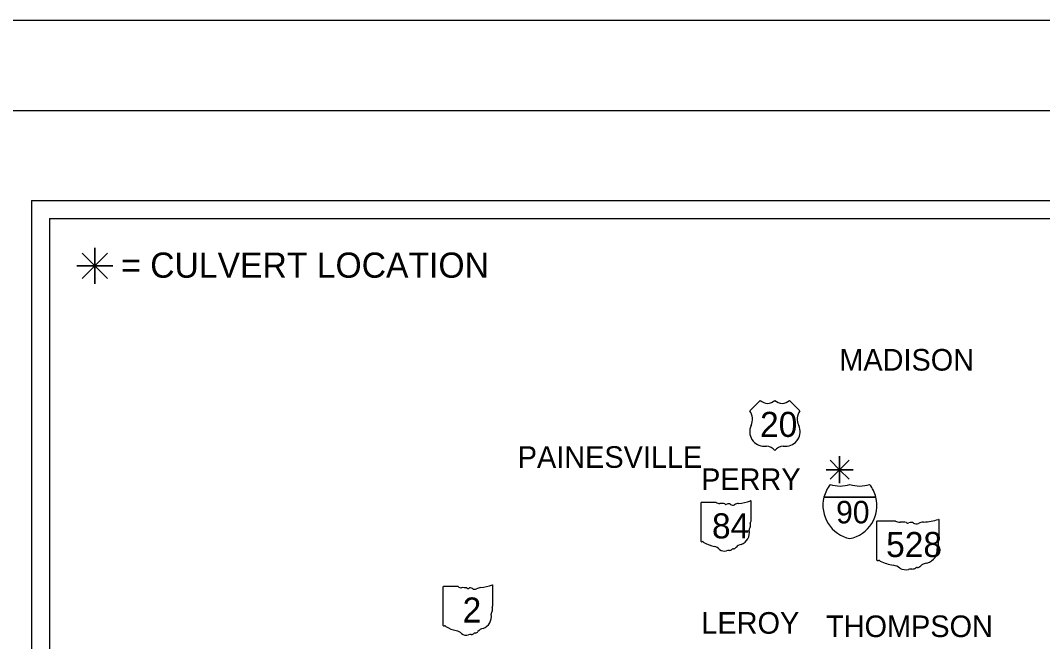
# Model space of a CAD drawing. Extents: x -1 to 48.3, y -9.3 to 22.
# Drawn here: x 1.94 to 7.62, y 18.55 to 22 of the extents above; entities that cross this region are included whole.
import ezdxf

# ---------------------------------------------------------------- set-up
doc = ezdxf.new("R2010")
doc.units = 0
for name, color, linetype in [('GM_X_Adjacent_County_Text', 7, 'Continuous'), ('GM_X_County', 7, 'Continuous'), ('GM_X_County_Road', 7, 'Continuous'), ('GM_X_Minor_Lake', 7, 'Continuous'), ('GM_X_Minor_Lake_Text', 7, 'Continuous'), ('GM_X_Minor_River_Text', 7, 'Continuous'), ('GM_X_Township', 7, 'Continuous')]:
    doc.layers.add(name, color=color, linetype=linetype)

msp = doc.modelspace()

# ---------------------------------------------------------------- linework, layer by layer
at = {"layer": 'GM_X_Adjacent_County_Text'}
msp.add_lwpolyline([(0, 0), (34, 0), (34, 22), (0, 22)], close=True, dxfattribs=at)
at = {"layer": 'GM_X_County'}
for p, q in [((2, 21), (2, 14)), ((2, 21), (9, 21)), ((2.1, 20.9), (2.1, 14.1)), ((2.1, 20.9), (8.9, 20.9))]:
    msp.add_line(p, q, dxfattribs=at)
at = {"layer": 'GM_X_County_Road'}
for p, q in [((5.7217, 19.3193), (5.7217, 19.108)), ((5.806, 19.3229), (5.7245, 19.3229)), ((6.0002, 19.2176), (6.0002, 19.3282)), ((6.0001, 19.2176), (6.0002, 19.2176)), ((6.6978, 19.2155), (6.6978, 19.0042)), ((6.8032, 19.2191), (6.7013, 19.2191)), ((7.0459, 19.1138), (7.0459, 19.2244)), ((7.0458, 19.1138), (7.0459, 19.1138)), ((4.2872, 18.8519), (4.2872, 18.6405)), ((4.3715, 18.8555), (4.29, 18.8555)), ((4.5657, 18.7502), (4.5657, 18.8607)), ((4.5656, 18.7502), (4.5657, 18.7502))]:
    msp.add_line(p, q, dxfattribs=at)
for centre, radius, start, end in [((5.7249, 19.3197), 0.00323, 98.1301, 188.1301), ((5.8254, 19.3475), 0.0313, 231.6195, 271.1119), ((5.9386, 19.2584), 0.0594, 97.3462, 120.7689), ((5.901, 19.611), 0.2953, 275.8445, 288.9065), ((5.9971, 19.3286), 0.0031, 351.8621, 97.738), ((5.8358, 19.2043), 0.1123, 80.4867, 94.9883), ((5.8613, 19.3208), 0.00903, 219.7921, 297.1024), ((5.8746, 19.2964), 0.0188, 54.4667, 119.1411), ((5.8988, 19.3299), 0.0226, 233.8562, 294.8282), ((5.9995, 19.2095), 0.0048, 107.944, 210.337), ((5.9689, 19.1955), 0.0288, 340.033, 23.6496), ((5.9969, 19.2172), 0.00332, 289.6038, 7.7341), ((5.9175, 19.1573), 0.0739, 292.3089, 8.9858), ((6.0113, 19.1713), 0.021, 136.8065, 186.9296), ((5.725, 19.1075), 0.00325, 171.9584, 258.3066), ((5.7254, 19.1291), 0.0248, 267.339, 280.6039), ((5.7305, 19.0958), 0.00895, 29.7484, 93.2717), ((5.8436, 19.2856), 0.2132, 240.4129, 257.1985), ((5.78, 19.013), 0.0667, 47.1842, 75.836), ((5.8522, 19.0947), 0.0423, 230.7004, 286.2918), ((5.8766, 19.0217), 0.0348, 85.6951, 111.2099), ((5.8797, 19.0789), 0.0226, 268.777, 315.5493), ((5.9001, 19.0584), 0.00635, 65.7517, 132.6484), ((5.8974, 19.0875), 0.0239, 282.8732, 323.2771), ((5.9487, 19.0486), 0.0404, 94.4031, 142.5768), ((4.4665, 19.1436), 0.2953, 275.8445, 288.9065), ((4.5626, 18.8612), 0.0031, 351.8621, 97.738), ((4.2904, 18.8523), 0.00323, 98.1301, 188.1301), ((4.3909, 18.88), 0.0313, 231.6195, 271.1119), ((4.4013, 18.7369), 0.1123, 80.4867, 94.9883), ((4.4268, 18.8534), 0.00903, 219.7921, 297.1024), ((4.4401, 18.829), 0.0188, 54.4667, 119.1411), ((4.4643, 18.8625), 0.0226, 233.8562, 294.8282), ((4.5041, 18.791), 0.0594, 97.3462, 120.7689), ((4.5624, 18.7498), 0.00332, 289.6038, 7.7341), ((4.483, 18.6899), 0.0739, 292.3089, 8.9858), ((4.5768, 18.7039), 0.021, 136.8065, 186.9296), ((4.565, 18.7421), 0.0048, 107.944, 210.337), ((4.5344, 18.7281), 0.0288, 340.033, 23.6496), ((4.2905, 18.6401), 0.00325, 171.9584, 258.3066), ((4.2909, 18.6617), 0.0248, 267.339, 280.6039), ((4.296, 18.6284), 0.00895, 29.7484, 93.2717), ((4.4091, 18.8182), 0.2132, 240.4129, 257.1985), ((4.3455, 18.5456), 0.0667, 47.1842, 75.836), ((4.4177, 18.6273), 0.0423, 230.7004, 286.2918), ((4.4421, 18.5542), 0.0348, 85.6951, 111.2099), ((4.4452, 18.6115), 0.0226, 268.777, 315.5493), ((4.4656, 18.591), 0.00635, 65.7517, 132.6484), ((4.4629, 18.6201), 0.0239, 282.8732, 323.2771), ((4.5142, 18.5812), 0.0404, 94.4031, 142.5768)]:
    msp.add_arc(centre, radius, start, end, dxfattribs=at)
for centre, major_axis, start_param, end_param in [((6.7018, 19.2159), (0.00403, 0), 1.712693, 3.28349), ((6.8275, 19.2437), (0.0391, 0), 4.042523, 4.731795), ((6.8404, 19.1005), (0.1404, 0), 1.404758, 1.657858), ((6.8723, 19.217), (0.0113, 0), 3.836095, 5.185415), ((6.8889, 19.1926), (0.0235, 0), 0.950623, 2.079405), ((6.9191, 19.2261), (0.0282, 0), 4.081561, 5.145723), ((6.969, 19.1546), (0.0743, 0), 1.699011, 2.107814), ((6.9219, 19.5072), (0.3691, 0), 4.814394, 5.042369), ((7.042, 19.2248), (0.00387, 0), 6.141152, 7.989035), ((7.045, 19.1057), (0.006, 0), 1.883978, 3.671073), ((7.0068, 19.0917), (0.036, 0), 5.934695, 6.695948), ((7.0417, 19.1134), (0.00415, 0), 5.05454, 6.418171), ((6.9426, 19.0535), (0.0923, 0), 5.101752, 6.440018), ((7.0598, 19.0675), (0.0262, 0), 2.387724, 3.262537), ((6.7019, 19.0037), (0.00407, 0), 3.00124, 4.508301), ((6.7025, 19.0253), (0.031, 0), 4.665946, 4.897461), ((6.7088, 18.992), (0.0112, 0), 0.519207, 1.627899), ((6.8501, 19.1818), (0.2665, 0), 4.195997, 4.488961), ((6.9815, 18.9448), (0.0506, 0), 1.647645, 2.488434), ((6.7707, 18.9092), (0.0834, 0), 0.823519, 1.323587), ((6.8609, 18.9909), (0.0529, 0), 4.026481, 4.996735), ((6.8915, 18.9179), (0.0435, 0), 1.495662, 1.94098), ((6.8953, 18.9751), (0.0282, 0), 4.691044, 5.507374), ((6.9208, 18.9546), (0.00794, 0), 1.147584, 2.315152), ((6.9174, 18.9837), (0.0298, 0), 4.937069, 5.64225)]:
    msp.add_ellipse(centre, major_axis=major_axis, ratio=0.8, start_param=start_param, end_param=end_param, dxfattribs=at)
at = {"layer": 'GM_X_Minor_Lake'}
msp.add_lwpolyline([(1.5, 21.5), (33.5, 21.5), (33.5, 0.5), (1.5, 0.5)], close=True, dxfattribs=at)
at = {"layer": 'GM_X_Minor_Lake_Text'}
for p, q in [((6.4055, 19.3517), (6.694, 19.3517)), ((6.694, 19.3517), (6.4055, 19.3517)), ((6.694, 19.3517), (6.4055, 19.3517))]:
    msp.add_line(p, q, dxfattribs=at)
for centre, start, end in [((6.5872, 19.3057), 141.669, 165.8066), ((6.4949, 19.6013), 253.0091, 286.9909), ((6.6045, 19.6013), 253.0091, 286.9909), ((6.5122, 19.3057), 14.1934, 38.331), ((6.5872, 19.3057), 165.8066, 258.463), ((6.5122, 19.3057), 281.537, 14.1934)]:
    msp.add_arc(centre, 0.1875, start, end, dxfattribs=at)
at = {"layer": 'GM_X_Minor_River_Text'}
for p, q in [((6.0513, 19.8897), (5.9933, 19.8317)), ((6.2718, 19.8317), (6.2138, 19.8897)), ((6.0745, 19.6344), (6.0861, 19.6344)), ((6.1789, 19.6344), (6.1906, 19.6344))]:
    msp.add_line(p, q, dxfattribs=at)
for centre, radius, start, end in [((6.0919, 19.9311), 0.058, 225.573, 314.427), ((6.1731, 19.9311), 0.058, 225.573, 314.427), ((5.9268, 19.7851), 0.0812, 334.5471, 35.0009), ((6.3383, 19.7851), 0.0812, 144.9991, 205.4529), ((6.0736, 19.7156), 0.0812, 154.8319, 270.6383), ((6.1915, 19.7156), 0.0812, 269.3617, 25.1681), ((6.0861, 19.5764), 0.058, 36.8699, 90), ((6.1789, 19.5764), 0.058, 90, 143.1301)]:
    msp.add_arc(centre, radius, start, end, dxfattribs=at)
at = {"layer": 'GM_X_Township'}
for points in [[(2.2526, 20.6366), (2.3526, 20.6366), (2.2819, 20.7073), (2.3526, 20.6366), (2.3526, 20.7366), (2.3526, 20.6366), (2.4233, 20.7073), (2.3526, 20.6366), (2.4526, 20.6366), (2.3526, 20.6366), (2.4233, 20.5659), (2.3526, 20.6366), (2.3526, 20.5366), (2.3526, 20.6366), (2.2819, 20.5659), (2.3526, 20.6366)], [(6.4172, 19.5043), (6.4922, 19.5043), (6.4391, 19.5574), (6.4922, 19.5043), (6.4922, 19.5793), (6.4922, 19.5043), (6.5452, 19.5574), (6.4922, 19.5043), (6.5672, 19.5043), (6.4922, 19.5043), (6.5452, 19.4513), (6.4922, 19.5043), (6.4922, 19.4293), (6.4922, 19.5043), (6.4391, 19.4513), (6.4922, 19.5043)]]:
    msp.add_lwpolyline(points, close=True, dxfattribs=at)

# ---------------------------------------------------------------- texts
at = {"layer": 'GM_X_County_Road'}
for s, height, p in [('84', 0.13922, (5.7831, 19.1229)), ('528', 0.13922, (6.751, 19.0191)), ('2', 0.1392, (4.3969, 18.6554))]:
    msp.add_text(s, height=height, dxfattribs=at).set_placement(p)
at = {"layer": 'GM_X_Minor_Lake_Text'}
msp.add_text('90', height=0.125, dxfattribs=at).set_placement((6.4727, 19.2063))
at = {"layer": 'GM_X_Minor_River_Text'}
msp.add_text('20', height=0.13922, dxfattribs=at).set_placement((6.0502, 19.6866))
at = {"layer": 'GM_X_Township'}
msp.add_text('= CULVERT LOCATION', height=0.14, dxfattribs=at).set_placement((2.499, 20.5708))
for s, p in [('MADISON', (6.4908, 20.055)), ('PAINESVILLE', (4.7033, 19.5148)), ('PERRY', (5.7227, 19.3916)), ('LEROY', (5.7241, 18.5933)), ('THOMPSON', (6.4171, 18.5747))]:
    msp.add_text(s, height=0.12, rotation=0, dxfattribs=at).set_placement(p)

doc.saveas('drawing.dxf')
